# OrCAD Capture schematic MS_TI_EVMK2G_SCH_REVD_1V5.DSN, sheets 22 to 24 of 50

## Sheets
22 21. HDMI TRANSMITTER: size C; title: HDMI TRASMITTER
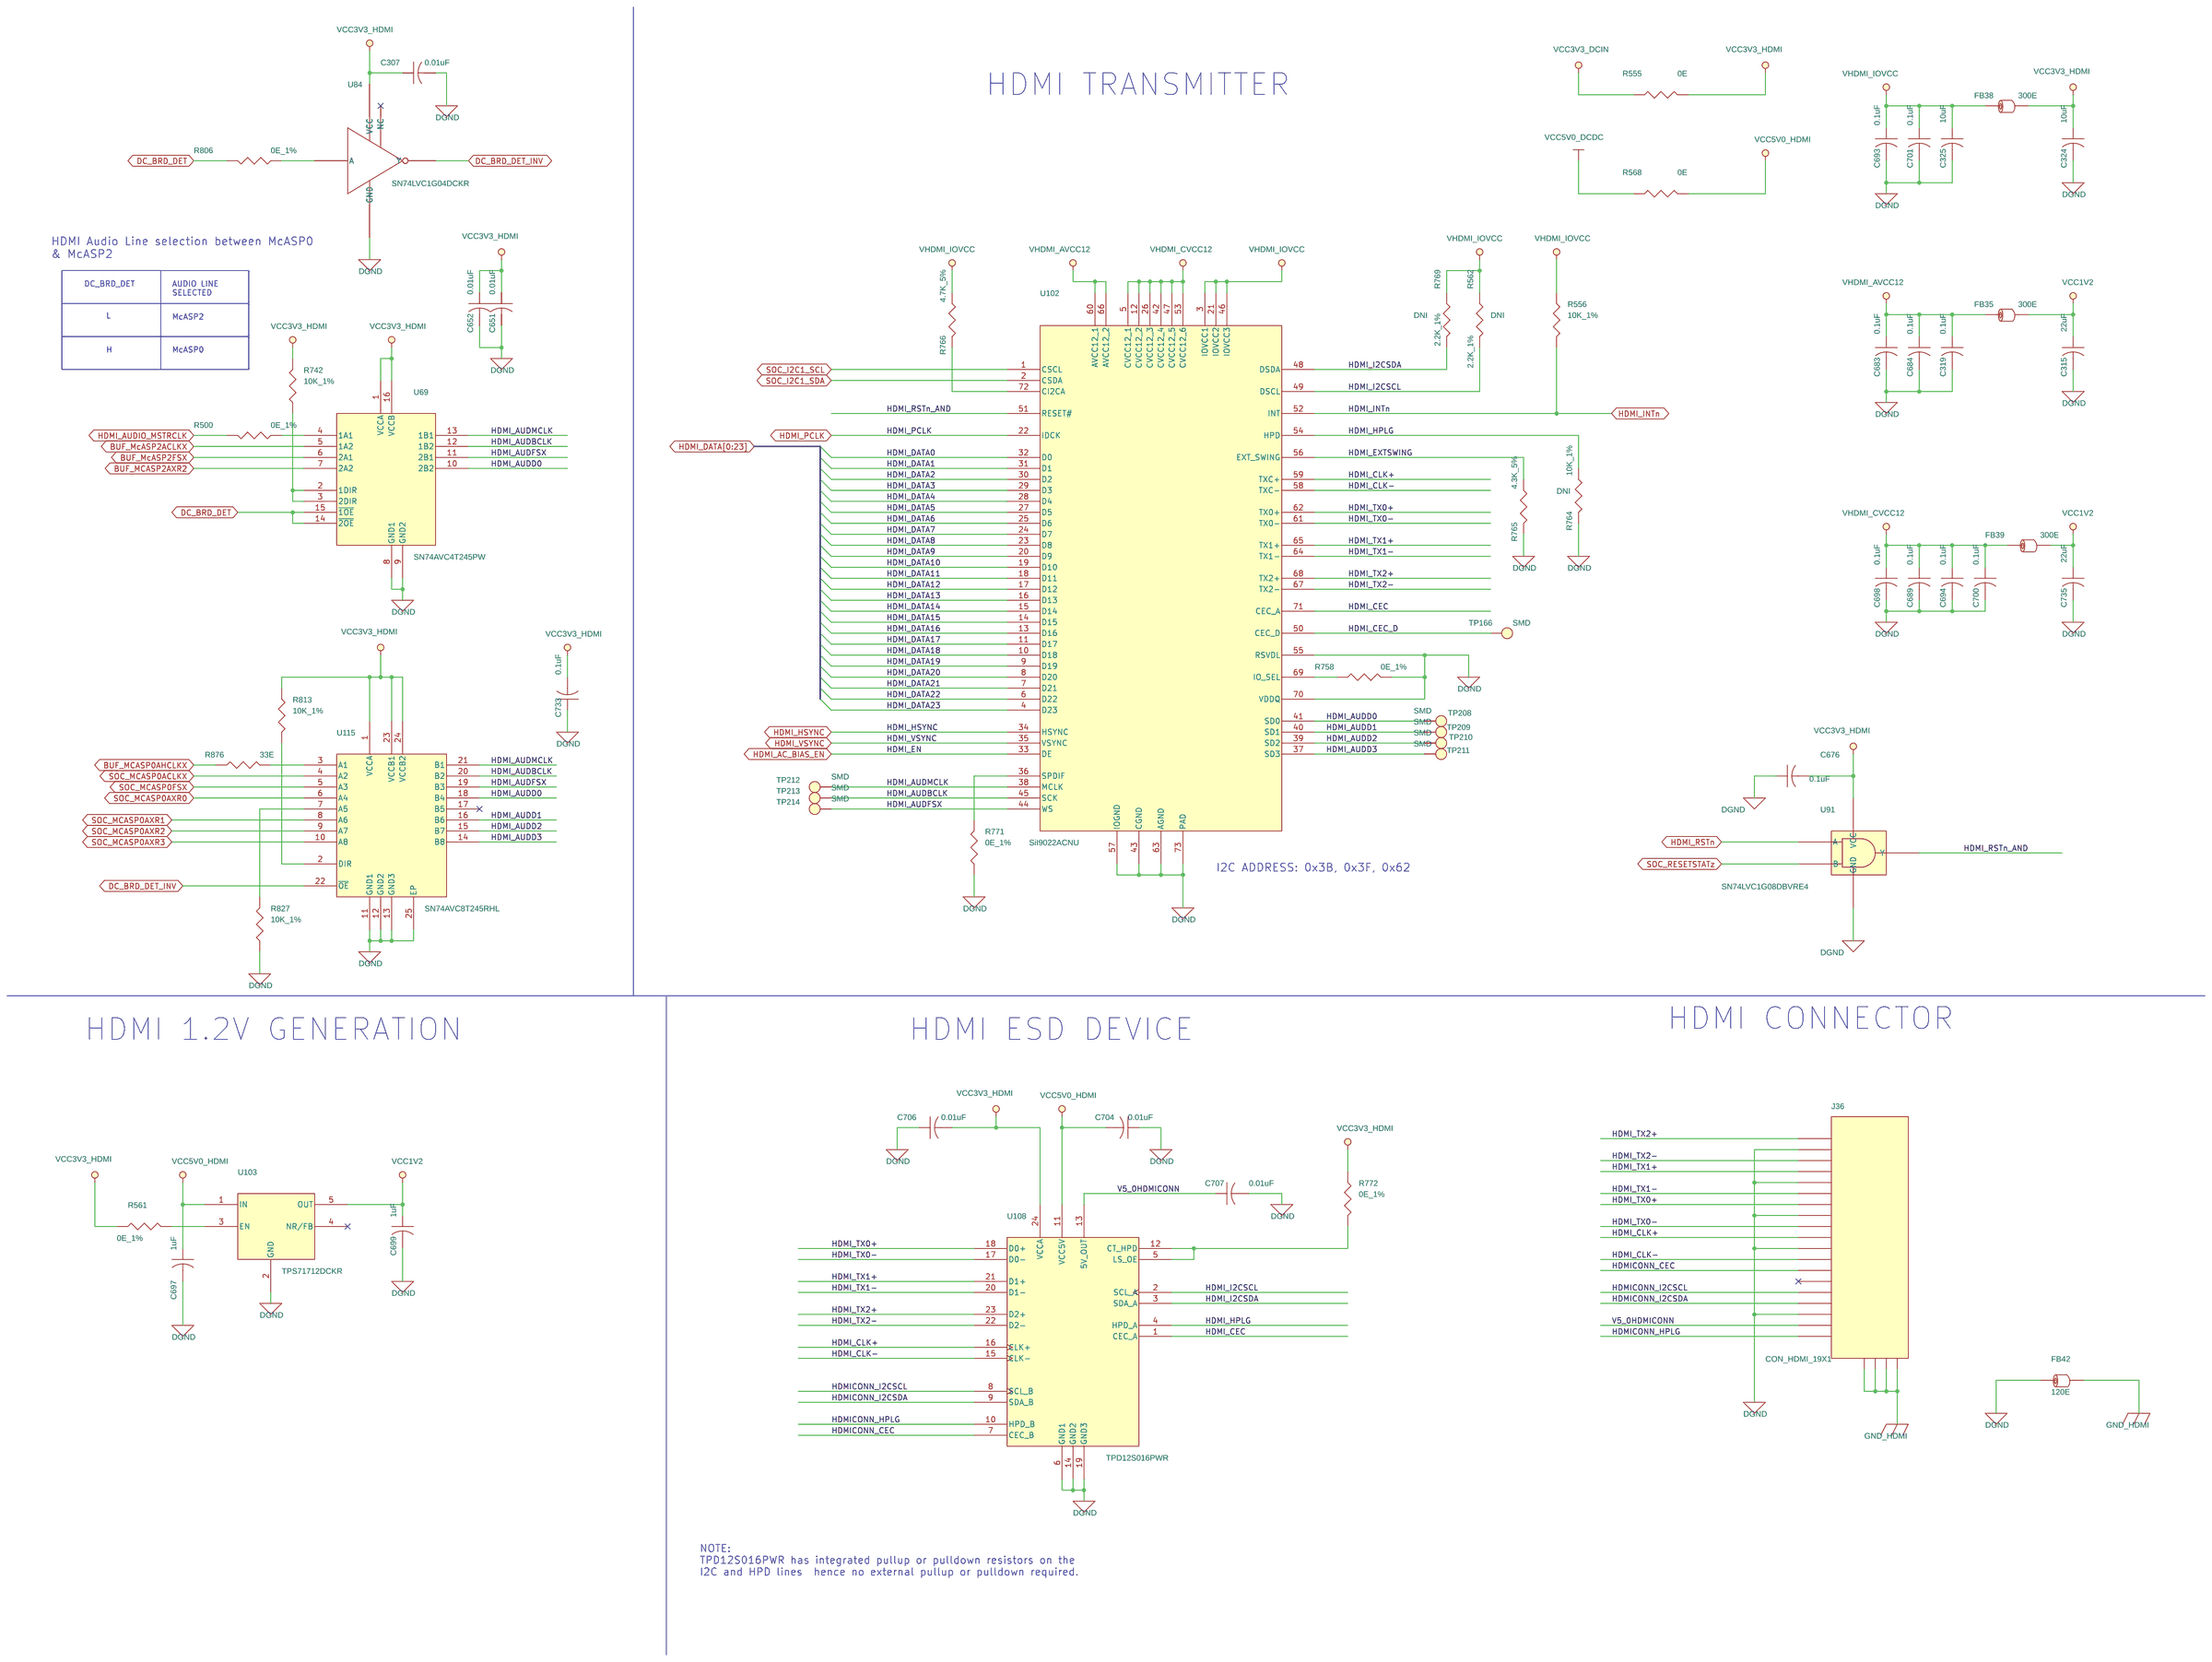
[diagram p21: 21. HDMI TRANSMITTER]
23 22. AUDIO CODEC: size C; title: AUDIO CODEC
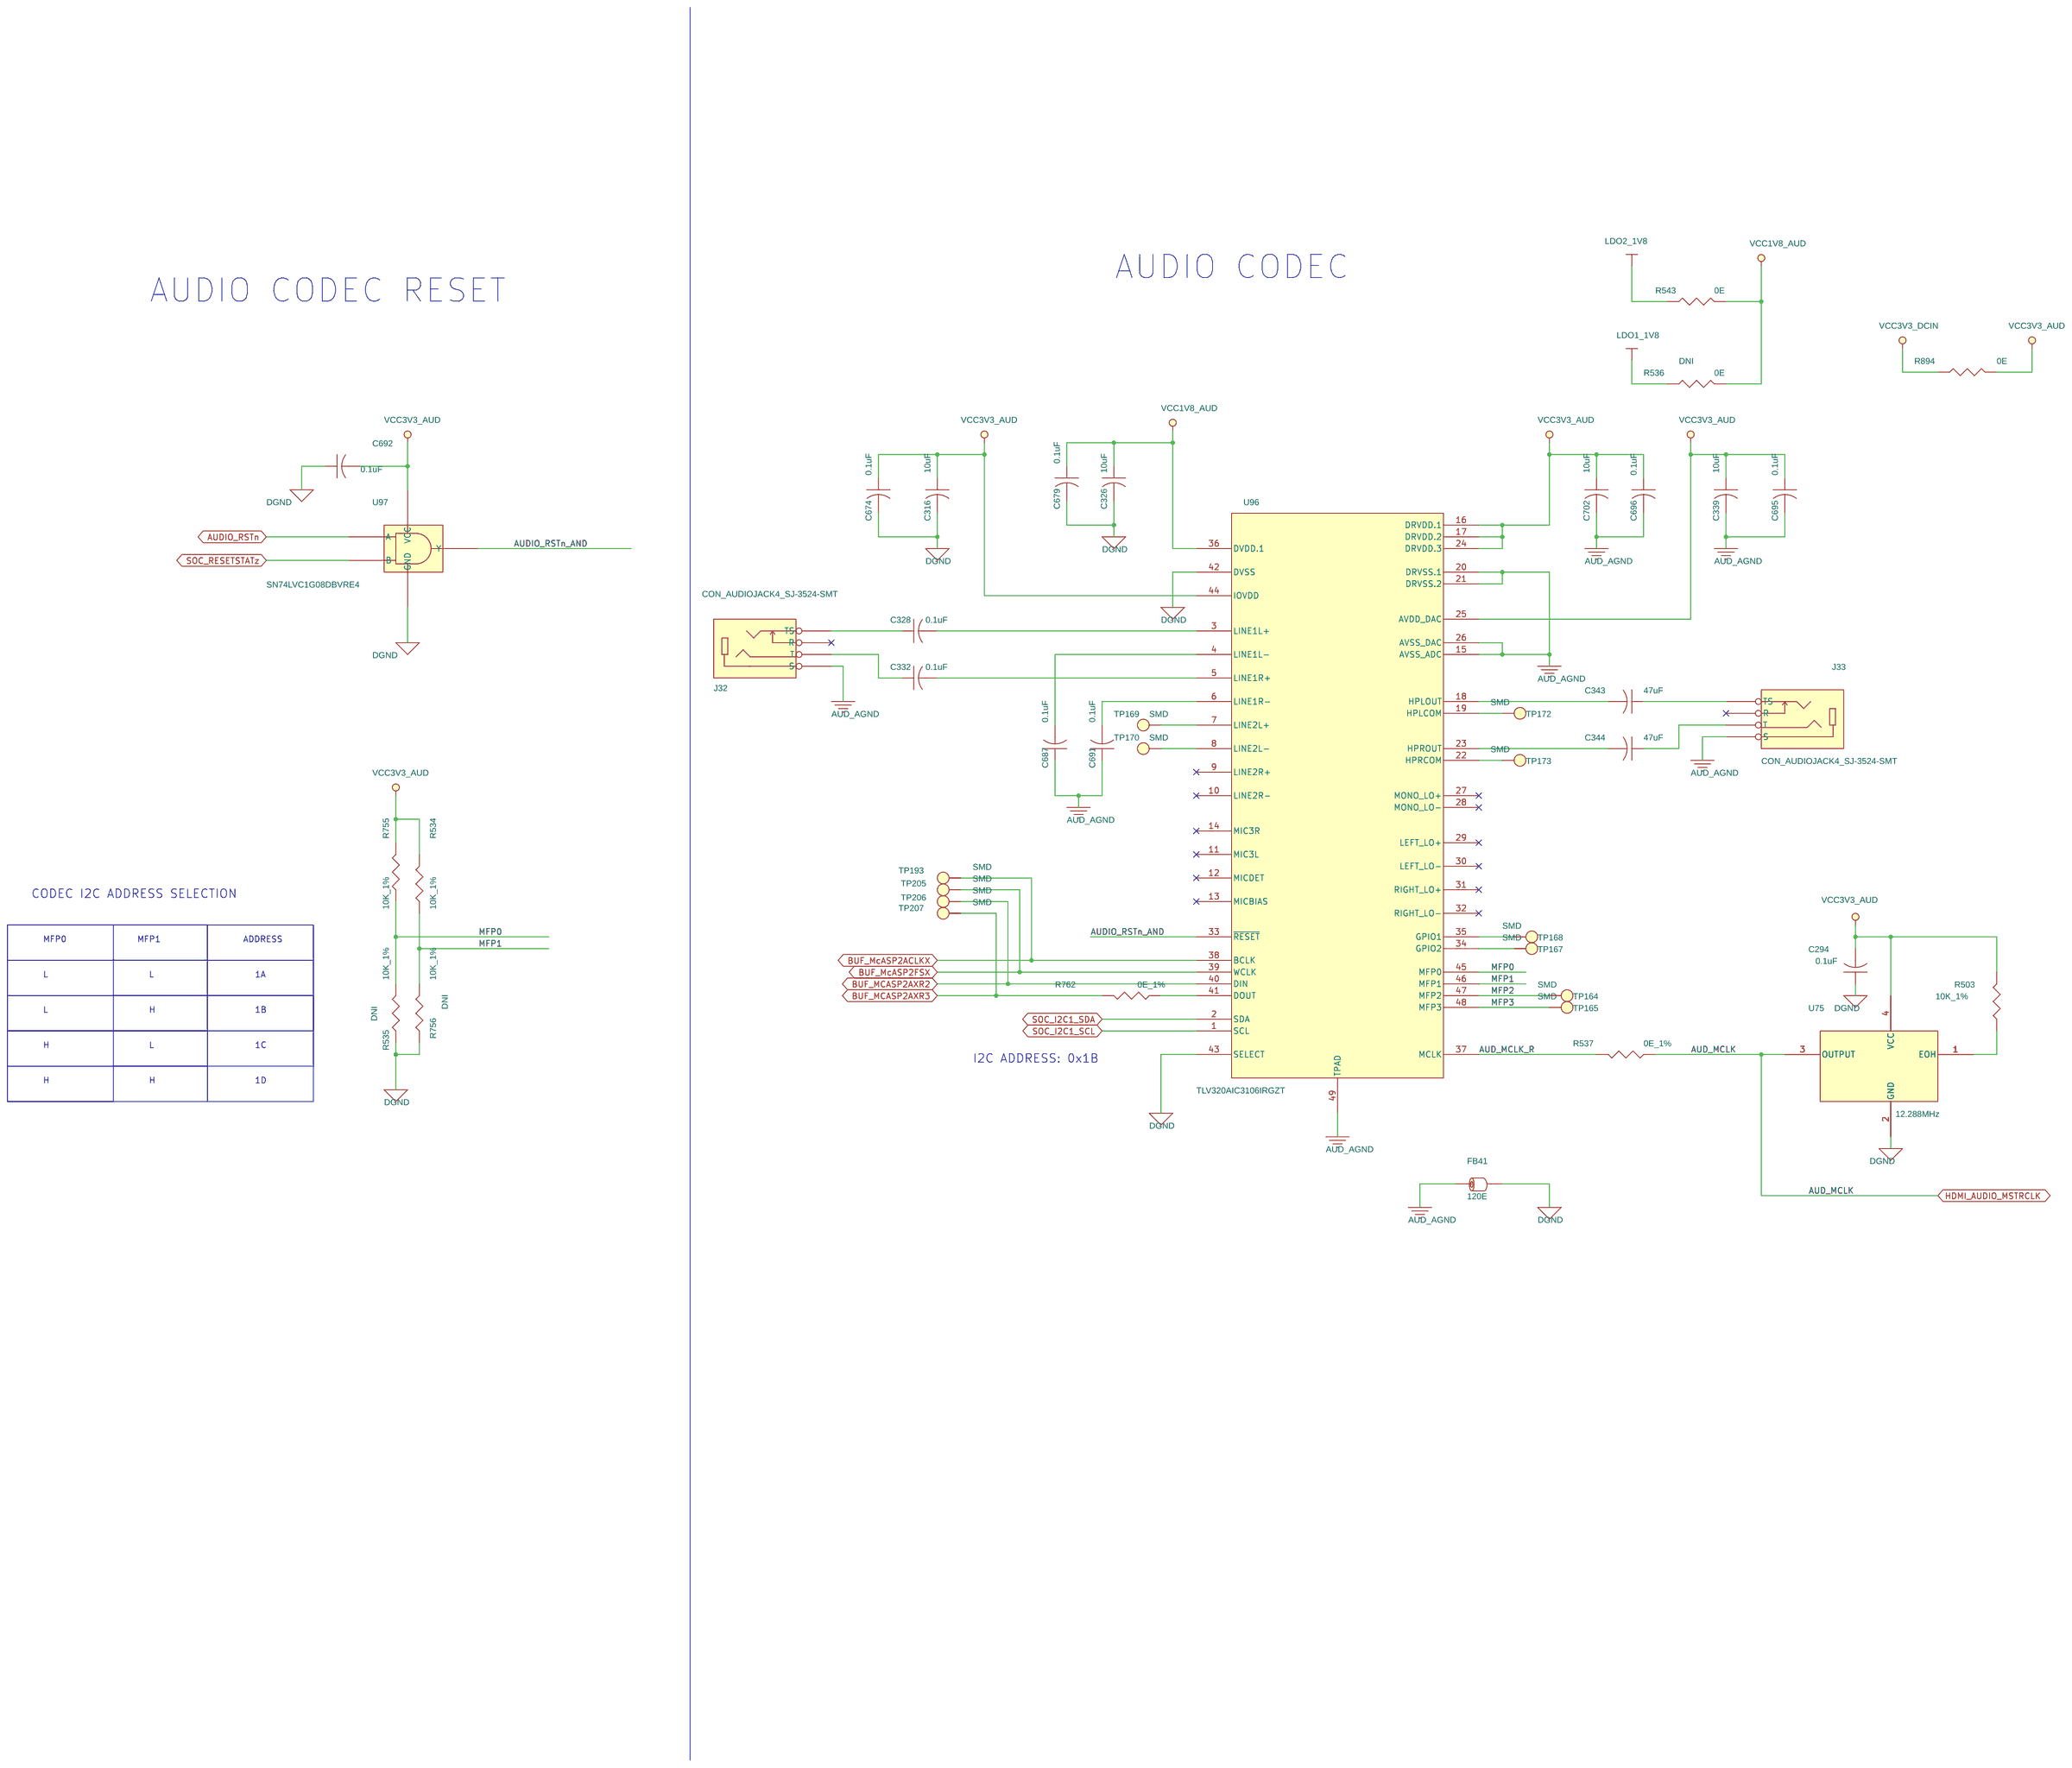
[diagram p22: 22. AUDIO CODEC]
24 23. AUDIO BUFFERS: size C; title: MCASP2 BUFFERS FOR COM8 , HDMI& AUDIO CODEC
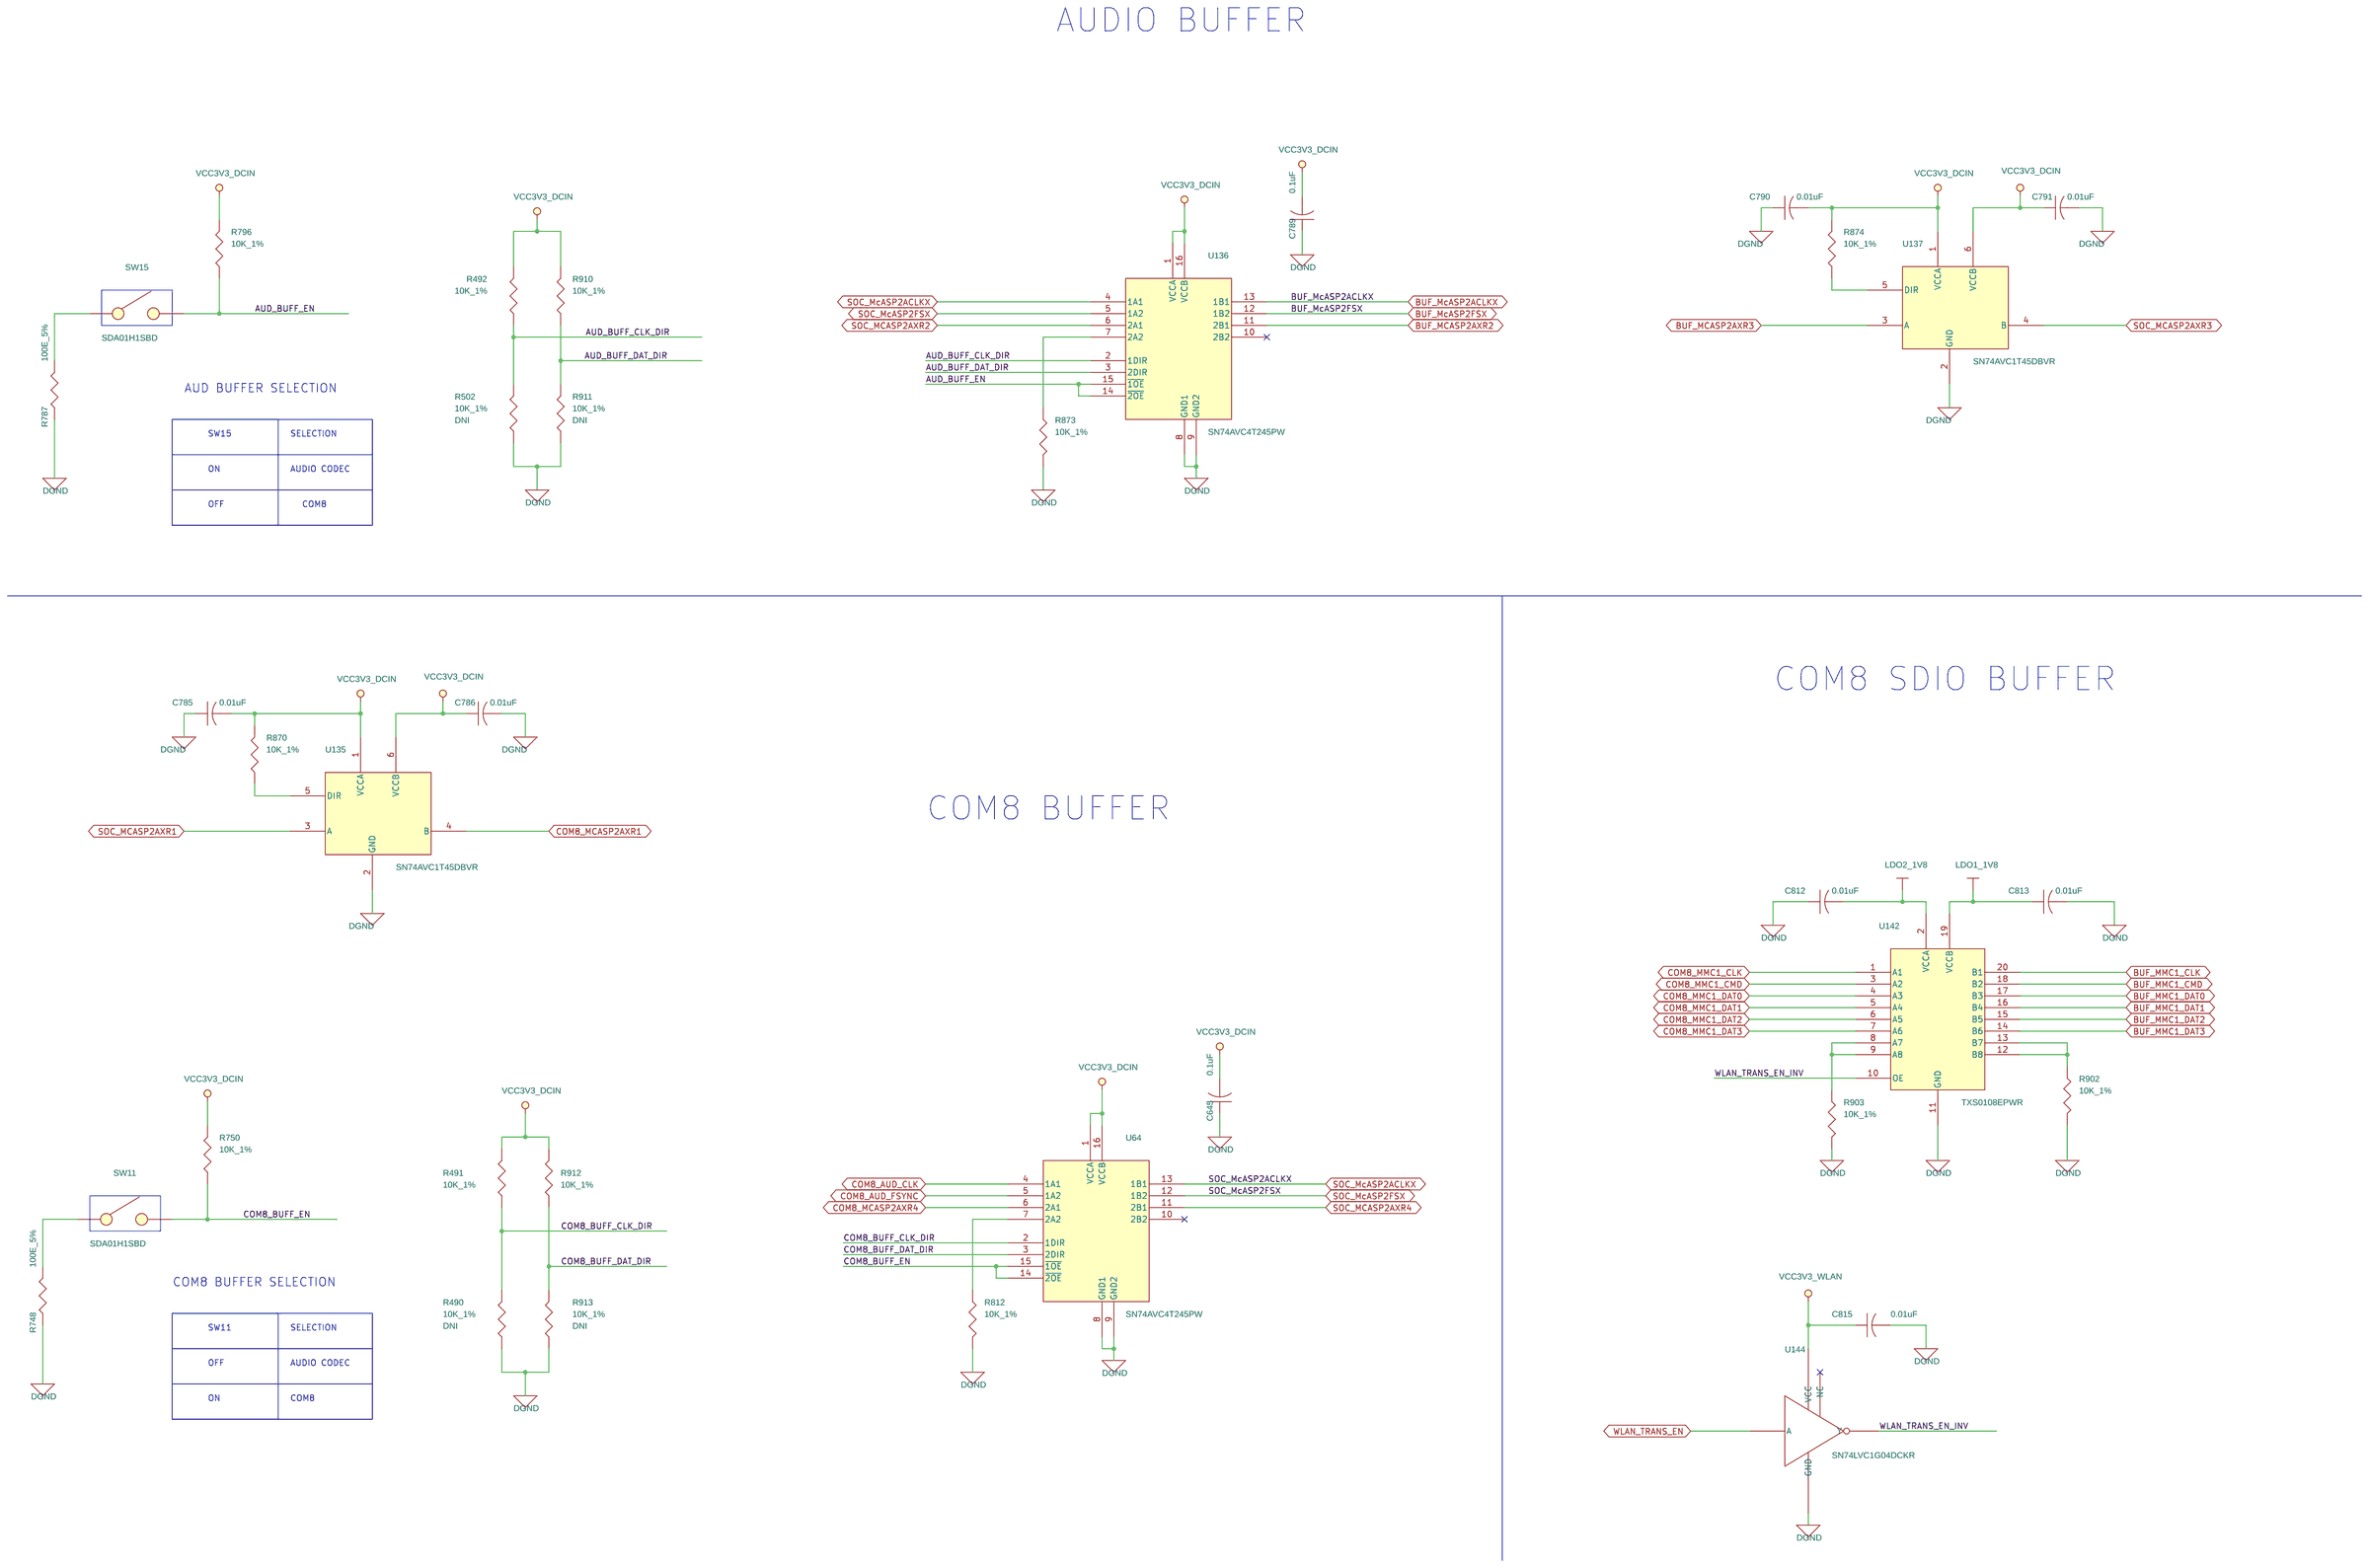
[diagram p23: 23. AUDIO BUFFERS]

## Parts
sheet 21. HDMI TRANSMITTER
C307  0.01uF  [CAP0402]
C315  22uF  [CAP0805]
C319  0.1uF  [CAP0402]
C324  10uF  [CAP0805]
C325  10uF  [CAP0805]
C651  0.01uF  [CAP0402]
C652  0.01uF  [CAP0201]
C676  0.1uF  [CAP0402]
C683  0.1uF  [CAP0402]
C684  0.1uF  [CAP0402]
C689  0.1uF  [CAP0402]
C693  0.1uF  [CAP0402]
C694  0.1uF  [CAP0402]
C697  1uF  [CAP0402]
C698  0.1uF  [CAP0402]
C699  1uF  [CAP0402]
C700  0.1uF  [CAP0402]
C701  0.1uF  [CAP0402]
C704  0.01uF  [CAP0402]
C706  0.01uF  [CAP0402]
C707  0.01uF  [CAP0402]
C733  0.1uF  [CAP0402]
C735  22uF  [CAP0805]
FB35  300E  [IND0603]
FB38  300E  [IND0603]
FB39  300E  [IND0603]
FB42  120E  [IND0402]
J36  CON_HDMI_19X1  [CON_19X1_10029449-001RLF_S_R_S]
R500  0E_1%  [RES0402]
R555  0E  [RES0402]
R556  10K_1%  [RES0402]
R561  0E_1%  [RES0402]
R562  2.2K_1%  [RES0402]
R568  0E  [RES0402]
R742  10K_1%  [RES0402]
R758  0E_1%  [RES0402]
R764  10K_1%  [RES0402]
R765  4.3K_5%  [RES0402]
R766  4.7K_5%  [RES0402]
R769  2.2K_1%  [RES0402]
R771  0E_1%  [RES0402]
R772  0E_1%  [RES0402]
R806  0E_1%  [RES0402]
R813  10K_1%  [RES0402]
R827  10K_1%  [RES0402]
R876  33E  [RES0402]
TP166  SMD  [TP20_SMD]
TP208  SMD  [TP40_SMD]
TP209  SMD  [TP40_SMD]
TP210  SMD  [TP40_SMD]
TP211  SMD  [TP40_SMD]
TP212  SMD  [TP40_SMD]
TP213  SMD  [TP40_SMD]
TP214  SMD  [TP40_SMD]
U69  SN74AVC4T245PW  [TSSOP16_25-59_205X180]
U84  SN74LVC1G04DCKR  [SC70-5]
U91  SN74LVC1G08DBVRE4  [SOT23-5]
U102  SiI9022ACNU  [QFN72_19-68_395X395]
U103  TPS71712DCKR  [SC70-5]
U108  TPD12S016PWR  [TSSOP24_25-59_315X180]
U115  SN74AVC8T245RHL  [QFN24_19-68_225X145]
sheet 22. AUDIO CODEC
C294  0.1uF  [CAP0402]
C316  10uF  [CAP0805]
C326  10uF  [CAP0805]
C328  0.1uF  [CAP0402]
C332  0.1uF  [CAP0402]
C339  10uF  [CAP0805]
C343  47uF  [CAP1206]
C344  47uF  [CAP1206]
C674  0.1uF  [CAP0402]
C679  0.1uF  [CAP0402]
C687  0.1uF  [CAP0402]
C691  0.1uF  [CAP0402]
C692  0.1uF  [CAP0402]
C695  0.1uF  [CAP0402]
C696  0.1uF  [CAP0402]
C702  10uF  [CAP0805]
FB41  120E  [IND0402]
J32  CON_AUDIOJACK4_SJ-3524-SMT  [CON_AV4_SJ-3524-SMT-1_R_S]
J33  CON_AUDIOJACK4_SJ-3524-SMT  [CON_AV4_SJ-3524-SMT-1_R_S]
R503  10K_1%  [RES0402]
R534  10K_1%  [RES0402]
R535  10K_1%  [RES0402]
R536  0E  [RES0402]
R537  0E_1%  [RES0402]
R543  0E  [RES0402]
R755  10K_1%  [RES0402]
R756  10K_1%  [RES0402]
R762  0E_1%  [RES0402]
R894  0E  [RES0402]
TP164  SMD  [TP40_SMD]
TP165  SMD  [TP40_SMD]
TP167  SMD  [TP40_SMD]
TP168  SMD  [TP40_SMD]
TP169  SMD  [TP40_SMD]
TP170  SMD  [TP40_SMD]
TP172  SMD  [TP40_SMD]
TP173  SMD  [TP40_SMD]
TP193  SMD  [TP40_SMD]
TP205  SMD  [TP40_SMD]
TP206  SMD  [TP40_SMD]
TP207  SMD  [TP40_SMD]
U75  12.288MHz  [OSC4_CB3_305X205_SMD]
U96  TLV320AIC3106IRGZT  [VQFN48_19-68_285X285]
U97  SN74LVC1G08DBVRE4  [SOT23-5]
sheet 23. AUDIO BUFFERS
C645  0.1uF  [CAP0402]
C785  0.01uF  [CAP0402]
C786  0.01uF  [CAP0402]
C789  0.1uF  [CAP0402]
C790  0.01uF  [CAP0402]
C791  0.01uF  [CAP0402]
C812  0.01uF  [CAP0402]
C813  0.01uF  [CAP0402]
C815  0.01uF  [CAP0402]
R490  10K_1%  [RES0402]
R491  10K_1%  [RES0402]
R492  10K_1%  [RES0402]
R502  10K_1%  [RES0402]
R748  100E_5%  [RES0402]
R750  10K_1%  [RES0402]
R787  100E_5%  [RES0402]
R796  10K_1%  [RES0402]
R812  10K_1%  [RES0402]
R870  10K_1%  [RES0402]
R873  10K_1%  [RES0402]
R874  10K_1%  [RES0402]
R902  10K_1%  [RES0402]
R903  10K_1%  [RES0402]
R910  10K_1%  [RES0402]
R911  10K_1%  [RES0402]
R912  10K_1%  [RES0402]
R913  10K_1%  [RES0402]
SW11  SDA01H1SBD  [SW2_100X324-80_180X300_SMD]
SW15  SDA01H1SBD  [SW2_100X324-80_180X300_SMD]
U64  SN74AVC4T245PW  [TSSOP16_25-59_205X180]
U135  SN74AVC1T45DBVR  [SOT23-6]
U136  SN74AVC4T245PW  [TSSOP16_25-59_205X180]
U137  SN74AVC1T45DBVR  [SOT23-6]
U142  TXS0108EPWR  [TSSOP20_25-59_260X180]
U144  SN74LVC1G04DCKR  [SC70-5]

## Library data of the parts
C307 C651 C704 C706 C707 C785 C786 C790 C791 C812 C813 C815 = CAP: CAP CERAMIC 0.01uF 16V 10% X7R 0402; Alternate_mfr_name_A: AVX CORPORATION; Alternate_mfr_name_B: KEMET; Alternate_mfr_name_D: TDK CORPORATION; Alternate_mfr_part_number_A: 0402YC103KAT2A; Alternate_mfr_part_number_B: C0402C103K4RACTU; Alternate_mfr_part_number_D: C1005X7R1C103K; Chkd/date: SHREESHAIL/180506; Crtd /date: MAZHAR/110506; Custom_Duty: 15%; Customs_HS_Code: 85322990; Distributor_name: DIGIKEY; Distributor_name_A: DIGIKEY; Distributor_name_B: DIGIKEY; Distributor_name_D: DIGIKEY; Distributor_part_number: PCC103BQCT-ND; Distributor_part_number_A: 478-1114-1-ND; Distributor_part_number_B: 399-1038-1-ND; Distributor_part_number_D: 445-1262-1-ND; Height: 0.55MM; Mfr_name: PANASONIC-ECG; Mfr_part_number: ECJ-0EB1C103K; Mistral Part No: 120009030032-R; Package: 0402; Part_type: CAPACITORS\CERAMIC; Project: VOCERA; RoHS: RoHS; Tolerance: 10%; Voltage: 16V; Datasheet: Y:\MIS_DATABASE\DATASHEETS\CAPACITORS\PAN-ECJ.PDF
C315 C735 = CAP: CAP CERAMIC 22uF 16V 10% X5R 0805; Chkd/date: MAZHAR/291110; Crtd /date: BAVISH/271110; Custom_Duty: 15%; Customs_HS_Code: 85322990; Distributor_name: NA; Distributor_part_number: NA; Height: 1.45MM; Mfr_name: TDK CORPORATION; Mfr_part_number: C2012X5R1C226K; Mistral Part No: 120010110025-R; Package: 0805; Part_type: CAPACITORS\CERAMIC; Project: EM-FLS; RoHS: RoHS; Temperature: -55°C+85°C; Tolerance: 10%; Voltage: 16V; Wattage: NA; Weight: NA; Datasheet: Y:\MIS_DATABASE\DATASHEETS\CAPACITORS\C2012.PDF
C294 C319 C328 C332 C645 C674 C676 C679 C683 C684 C687 C689 C691-C696 C698 C700 C701 C733 C789 = CAP: CAP CERAMIC 0.1uF 16V 10% X7R 0402; Alternate_mfr_name_A: KEMET; Alternate_mfr_part_number_A: C0402C104K4RACT; Chkd/date: MAZHAR/281108; Crtd /date: MAZHAR/030907; Custom_Duty: 15%; Customs_HS_Code: 85322990; Distributor_name: DIGIKEY; Distributor_name_A: DIGIKEY; Distributor_part_number: 490-3261-1-ND; Distributor_part_number_A: 399-3521-1-ND; Height: 0.55MM; Mfr_name: MURATA; Mfr_part_number: GRM155R71C104KA88D; Mistral Part No: 120009030060-R; Package: 0402; Part_type: CAPACITORS\CERAMIC; Project: SMART VIEW_IP CAMERA; Tolerance: 10%; Voltage: 16V; Datasheet: Y:\MIS_DATABASE\DATASHEETS\CAPACITORS\GRM188SERIES.PDF
C316 C324-C326 C339 C702 = CAP: CAP CERAMIC 10uF 16V 10% X5R 0805; Alternate_mfr_name_A: TAIYO YUDEN; Alternate_mfr_part_number_A: EMK212BJ106KG-T; Chkd/date: RAVI/020511; Crtd /date: BAVISH/290411; Custom_Duty: 15%; Customs_HS_Code: 85322990; Distributor_name: DIGIKEY; Distributor_name_A: DIGIKEY; Distributor_part_number: 478-5165-1-ND; Distributor_part_number_A: 587-1295-1-ND; Height: 1.40MM; Mfr_name: AVX CORPORATION; Mfr_part_number: 0805YD106KAT2A; Mistral Part No: 120011040011-R; Package: 0805; Part_type: CAPACITORS\CERAMIC; Project: AOD_POD-RF; RoHS: RoHS; Temperature: -55°C+85°C; Tolerance: 10%; Voltage: 16V; Wattage: NA; Weight: NA; Datasheet: Y:\MIS_DATABASE\DATASHEETS\CAPACITORS\AVX_CERAMIC.PDF
C652 = CAP: CAP CERAMIC 0.01uF 10V 10% X5R 0201; Chkd/date: MAZHAR/010211; Crtd /date: BAVISH/131010; Custom_Duty: 15%; Customs_HS_Code: 85322990; Distributor_name: DIGIKEY; Distributor_part_number: 445-1793-1-ND; Height: 0.33MM; Mfr_name: TDK CORPORATION; Mfr_part_number: C0603X5R1A103K; Mistral Part No: 120011010015-R; Package: 0201; Part_type: CAPACITORS\CERAMIC; Project: IDMATEK2; RoHS: RoHS; Temperature: -55°C+85°C; Tolerance: 10%; Voltage: 10V; Wattage: NA; Weight: NA; Datasheet: Y:\MIS_DATABASE\DATASHEETS\CAPACITORS\TDK_CAP.PDF
C697 C699 = CAP: CAP CERAMIC 1uF 10V 10% X5R 0402; Chkd/date: BALACHANDAR/160514; Crtd /date: SARANYA/060514; Custom_Duty: 15%; Customs_HS_Code: 85322990; Distributor_name: DIGIKEY; Distributor_part_number: 478-4596-1-ND; Height: 0.56MM; Mfr_name: AVX CORPORATION; Mfr_part_number: 0402ZD105KAT2A; Mistral Part No: 120014050010-R; Package: 0402; Part_type: CAPACITORS\CERAMIC; Project: AEGIS GP BETA2; RoHS: RoHS; Temperature: -55°C+85°C; Tolerance: 10%; Voltage: 10V; Wattage: NA; Weight: NA; Datasheet: Y:\MIS_DATABASE\DATASHEETS\CAPACITORS\AVX_MLC.PDF
FB35 FB38 FB39 = INDUCTOR_FERRITE: IND FERRITE CHIP 300E 500mA 0603; Chkd/date: VASANTHA/190614; Crtd /date: NAVEED/160614; Custom_Duty: 24%; Customs_HS_Code: 85437099; Distributor_name: DIGIKEY; Distributor_part_number: 445-2171-1-ND; Height: 0.75MM; Mfr_name: TDK CORPORATION; Mfr_part_number: MMZ1608R301A; Mistral Part No: 130014060028-R; Package: 0603; Part_type: INDUCTOR; Project: AEGIS_POM; RoHS: RoHS; Temperature: -55°C+125°C; Tolerance: NA; Voltage: NA; Wattage: NA; Weight: NA; Datasheet: Y:\MIS_DATABASE\DATASHEETS\DISCRETES\INDUCTORS\MMZSER.PDF
FB41 FB42 = INDUCTOR_FERRITE: IND BEAD CHIP 120E 1.2A 0402; Chkd/date: ASHOK/240212; Crtd /date: BAVISH/060711; Custom_Duty: 24%; Customs_HS_Code: 85437099; Distributor_name: DIGIKEY; Distributor_part_number: 445-2981-1-ND; Height: 0.55MM; Mfr_name: TDK CORPORATION; Mfr_part_number: MPZ1005S121C; Mistral Part No: 130011070007-R; Package: 0402; Part_type: INDUCTOR; Project: SVDU; RoHS: RoHS; Temperature: -40°C+85°C; Tolerance: NA; Voltage: NA; Wattage: NA; Weight: 1mg; Datasheet: Y:\MIS_DATABASE\DATASHEETS\DISCRETES\INDUCTORS\MPZ1005.PDF
J36 = CON_HDMI_19X1: CON RECEPTACLE HDMI TYPE A RT SMD; Chkd/date: SUHAS/290311; Crtd /date: MUDDU/060510; Custom_Duty: 24%; Customs_HS_Code: 85369090; Distributor_name: DIGIKEY; Distributor_part_number: 609-1010-1-ND; Height: 6.30MM; Mfr_name: FCI; Mfr_part_number: 10029449-001RLF; Mistral Part No: 150010050001; Package: SMD; Part_type: CONNECTOR\MISCELLANEOUS; Project: SHIVA; RoHS: RoHS; Temperature: NA; Weight: NA; Datasheet: Y:\MIS_DATABASE\DATASHEETS\CONNECTORS\10029449-001RLF.PDF
R500 R537 R561 R758 R762 R771 R772 R806 = RESISTOR: RES 0E 1/16W 1% 0402; Chkd/date: MAZHAR/220709; Crtd /date: USMAN/270109; Custom_Duty: 15%; Customs_HS_Code: 85332119; Distributor_name: NA; Distributor_part_number: NA; Height: 0.40MM; Mfr_name: YAGEO AMERICA; Mfr_part_number: RC0402FR-070RL; Mistral Part No: 110009030085-P; Package: 0402; Part_type: RESISTORS\FIXED; Project: OMAP_EVM; RoHS: Pb-Free; Tolerance: 1%; Wattage: 1/16W; Datasheet: Y:\MIS_DATABASE\DATASHEETS\RESISTORS\CRCW0603.PDF
R543 R555 R568 R894 = RESISTOR: RES 0E 1/10W 5% 0402; Chkd/date: NAVEED/241114; Crtd /date: NAVEED/201014; Custom_Duty: 15%; Customs_HS_Code: 85332119; Distributor_name: DIGIKEY; Distributor_part_number: P0.0JCT-ND; Height: 0.40MM; Mfr_name: PANASONIC-ECG; Mfr_part_number: ERJ-2GE0R00X; Mistral Part No: 110014100008-R; Package: 0402; Part_type: RESISTORS\FIXED; Project: AEGIS POM; RoHS: RoHS; Tolerance: 5%; Wattage: 1/10W; Datasheet: Y:\MIS_DATABASE\DATASHEETS\RESISTORS\ERJ12.PDF
R491 R492 R503 R534 R556 R742 R750 R755 R796 R812 R813 R827 R870 R873 R874 R902 R903 R910 R912 = RESISTOR: RES 10K 1/16W 1% 0402; Alternate_mfr_name_A: AVX CORPORATION; Alternate_mfr_name_B: PANASONIC-ECG-ECG; Alternate_mfr_name_C: YAGEO AMERICA; Alternate_mfr_name_D: VISHAY; Alternate_mfr_part_number_A: CR05-103F-H; Alternate_mfr_part_number_B: ERJ-2RKF1002X; Alternate_mfr_part_number_C: 9C04021A1002FLHF3; Alternate_mfr_part_number_D: CRCW040210K0FKED; Chkd/date: SHREESHAIL/310506; Crtd /date: GEETHA/290506; Custom_Duty: 15%; Customs_HS_Code: 85332119; Distributor_name: DIGIKEY; Distributor_name_A: NA; Distributor_name_B: DIGIKEY; Distributor_name_C: DIGIKEY; Distributor_name_D: DIGIKEY; Distributor_part_number: 311-10.0KLRTR-ND; Distributor_part_number_A: NA; Distributor_part_number_B: P10.0KLCT-ND; Distributor_part_number_C: 311-10.0KLCT-ND; Distributor_part_number_D: 541-10.0KLCT-ND; Height: 0.40MM; Mfr_name: YAGEO AMERICA; Mfr_part_number: RC0402FR-0710KL; Mistral Part No: 110009030220-P; Package: 0402; Part_type: RESISTORS\FIXED; Project: VOCERA; RoHS: Pb-Free; Tolerance: 1%; Wattage: 1/16W; Datasheet: Y:\MIS_DATABASE\DATASHEETS\RESISTORS\YAGEO-RC0402.PDF
R562 R769 = RESISTOR: RES 2.2K 1/16W 1% 0402; Chkd/date: NAVEED/241114; Crtd /date: VASANTHA/101114; Custom_Duty: 15%; Customs_HS_Code: 85332119; Distributor_name: DIGIKEY; Distributor_part_number: 311-2.20KLRCT-ND; Height: 0.40MM; Loading: DNI; Mfr_name: YAGEO AMERICA; Mfr_part_number: RC0402FR-072K2L; Mistral Part No: 110014110004-R; Package: 0402; Part_type: RESISTORS\FIXED; Project: GALILEO_EVM; RoHS: RoHS; Temperature: -55°C+155°C; Tolerance: 1%; Voltage: NA; Wattage: 1/16W; Weight: NA; Datasheet: Y:\MIS_DATABASE\DATASHEETS\RESISTORS\RC0402FR.PDF
R490 R502 R535 R756 R764 R911 R913 = RESISTOR: RES 10K 1/16W 1% 0402; Alternate_mfr_name_A: AVX CORPORATION; Alternate_mfr_name_B: PANASONIC-ECG-ECG; Alternate_mfr_name_C: YAGEO AMERICA; Alternate_mfr_name_D: VISHAY; Alternate_mfr_part_number_A: CR05-103F-H; Alternate_mfr_part_number_B: ERJ-2RKF1002X; Alternate_mfr_part_number_C: 9C04021A1002FLHF3; Alternate_mfr_part_number_D: CRCW040210K0FKED; Chkd/date: SHREESHAIL/310506; Crtd /date: GEETHA/290506; Custom_Duty: 15%; Customs_HS_Code: 85332119; Distributor_name: DIGIKEY; Distributor_name_A: NA; Distributor_name_B: DIGIKEY; Distributor_name_C: DIGIKEY; Distributor_name_D: DIGIKEY; Distributor_part_number: 311-10.0KLRTR-ND; Distributor_part_number_A: NA; Distributor_part_number_B: P10.0KLCT-ND; Distributor_part_number_C: 311-10.0KLCT-ND; Distributor_part_number_D: 541-10.0KLCT-ND; Height: 0.40MM; Loading: DNI; Mfr_name: YAGEO AMERICA; Mfr_part_number: RC0402FR-0710KL; Mistral Part No: 110009030220-P; Package: 0402; Part_type: RESISTORS\FIXED; Project: VOCERA; RoHS: Pb-Free; Tolerance: 1%; Wattage: 1/16W; Datasheet: Y:\MIS_DATABASE\DATASHEETS\RESISTORS\YAGEO-RC0402.PDF
R765 = RESISTOR: RES 4.3K 1/16W 5% 0402; Chkd/date: VASANTHA/190614; Crtd /date: NAVEED/160614; Custom_Duty: 15%; Customs_HS_Code: 85332119; Distributor_name: DIGIKEY; Distributor_part_number: RMCF0402JT4K30CT-ND; Height: 0.40MM; Mfr_name: STACKPOLE ELECTRONICS; Mfr_part_number: RMCF0402JT4K30; Mistral Part No: 110014060029-R; Package: 0402; Part_type: RESISTORS\FIXED; Project: AEGIS_POM; RoHS: RoHS; Temperature: -55°C+155°C; Tolerance: 5%; Voltage: NA; Wattage: 1/16W; Weight: NA; Datasheet: Y:\MIS_DATABASE\DATASHEETS\RESISTORS\RMCF-SERIES1.PDF
R766 = RESISTOR: RES 4.7K 1/16W 5% 0402; Chkd/date: VASANTHA/190614; Crtd /date: NAVEED/160614; Custom_Duty: 15%; Customs_HS_Code: 85332119; Distributor_name: DIGIKEY; Distributor_part_number: RMCF0402JT4K70CT-ND; Height: 0.40MM; Mfr_name: STACKPOLE ELECTRONICS; Mfr_part_number: RMCF0402JT4K70; Mistral Part No: 110014060028-R; Package: 0402; Part_type: RESISTORS\FIXED; Project: AEGIS_POM; RoHS: RoHS; Temperature: -55°C+155°C; Tolerance: 5%; Voltage: NA; Wattage: 1/16W; Weight: NA; Datasheet: Y:\MIS_DATABASE\DATASHEETS\RESISTORS\RMCF-SERIES1.PDF
R876 = RESISTOR: RES 33E 1/16W 5% 0402; Alternate_mfr_name_A: AVX CORPORATION; Alternate_mfr_name_B: ROHM; Alternate_mfr_name_C: YAGEO AMERICA; Alternate_mfr_name_D: YAGEO AMERICA; Alternate_mfr_part_number_A: CR05-330J-H; Alternate_mfr_part_number_B: MCR01MZPJ330; Alternate_mfr_part_number_C: 9C04021A33R0JLHF3; Alternate_mfr_part_number_D: RC0402JR-0733RL; Chkd/date: SHREESHAIL/200406; Crtd /date: GEETHA/190406; Custom_Duty: 15%; Customs_HS_Code: 85332119; Distributor_name: DIGIKEY; Distributor_name_A: NA; Distributor_name_B: DIGIKEY; Distributor_name_C: DIGIKEY; Distributor_name_D: DIGIKEY; Distributor_part_number: P33JCT-ND; Distributor_part_number_A: NA; Distributor_part_number_B: RHM33JCT-ND; Distributor_part_number_C: 311-33JCT-ND; Distributor_part_number_D: 311-33JRCT-ND; Height: 0.40MM; Mfr_name: PANASONIC-ECG; Mfr_part_number: ERJ-2GEJ330X; Mistral Part No: 110009030699-R; Package: 0402; Part_type: RESISTORS\FIXED; Project: RED EYE; RoHS: RoHS; Tolerance: 5%; Wattage: 1/16W; Datasheet: Y:\MIS_DATABASE\DATASHEETS\RESISTORS\ERJ12.PDF
TP166 = TESTPOINT: TESTPOINT 20 SMD; Chkd/date: SHREESHAIL/171006; Crtd /date: MAZHAR/171006; Distributor_name: NA; Distributor_part_number: NA; Height: NA; Mfr_name: LOCAL; Mistral Part No: NA4; Part_type: MISC\TESTPOINT; Project: BT MODULE_CSRBC04
TP164 TP165 TP167-TP170 TP172 TP173 TP193 TP205-TP214 = TESTPOINT: TESTPOINT 40 SMD; Chkd/date: MAZHAR/190505; Crtd /date: MAZHAR/190505; Distributor_name: NA; Distributor_part_number: NA; Height: NA; Mfr_name: LOCAL; Mistral Part No: 130009030933; Part_type: MISC\TESTPOINT; Project: RAINIER-3
U64 U69 U136 = SN74AVC4T245PW_TSSOP16: IC 4-BIT DUAL SUPPLY BUS TRANSCEIVER TSSOP16; Chkd/date: SHREESHAIL/030506; Crtd /date: MAZHAR/270406; Custom_Duty: 15%; Customs_HS_Code: 85423100; Distributor_name: MOUSER; Distributor_part_number: 595-SN74AVC4T245PW; Height: 1.20MM; Mfr_name: TEXAS INSTRUMENTS; Mistral Part No: 141009030111-R; Package: TSSOP16; Part_type: ICS\DIGITAL\COMBINATIONAL; Project: VOCERA; RoHS: Sb/ Br FREE; Datasheet: Y:\MIS_DATABASE\DATASHEETS\ICS\DIGITAL\BUSTRANSCEIVER\SN74AVC4T245.PDF
U84 U144 = SN74LVC1G04DCKR_SC70-5: IC SINGLE INVERTER GATE SC70-5; Chkd/date: SUHAS/221010; Crtd /date: USMAN/150709; Custom_Duty: 15%; Customs_HS_Code: 85423100; Distributor_name: DIGIKEY; Distributor_part_number: 296-11600-1-ND; Height: 1.10MM; Mfr_name: TEXAS INSTRUMENTS; Mistral Part No: 141009070007-R; Part_type: ICS\DIGITAL\GATES; Project: BUG_BASE-II; RoHS: Sb/ Br FREE; Temperature: -40°C+85°C; Datasheet: Y:\MIS_DATABASE\DATASHEETS\ICS\DIGITAL\GATES\SN74LVC1G04-1.PDF
U91 U97 = SN74LVC1G08DBVRE4_SOT23-5: IC SINGLE 2-INPUT POSITIVE AND GATE SOT23-5; Chkd/date: SUHAS/221010; Crtd /date: USMAN/151008; Custom_Duty: 15%; Customs_HS_Code: 85423100; Distributor_name: DIGIKEY; Distributor_part_number: SN74LVC1G08DBVRE4-ND; Height: 1.45MM; Mfr_name: TEXAS INSTRUMENTS; Mistral Part No: 141009060026-R; Part_type: ICS\DIGITAL\GATES; Project: KHAN_MAIN; RoHS: Sb/ Br FREE; Temperature: -40°C+85°C; Datasheet: Y:\MIS_DATABASE\DATASHEETS\ICS\DIGITAL\GATES\SN74LVC1G08.PDF
U102 = SiI9022ACNU_QFN72: IC HDMI TRANSMITTER QFN72; Chkd/date: VASANTHA/230714; Crtd /date: MUDDU/310510; Custom_Duty: 15%; Customs_HS_Code: 85423100; Distributor_name: NA; Distributor_part_number: NA; Height: 0.90MM; Mfr_name: SILICON IMAGE; Mistral Part No: 141010060001; Package: QFN72; Part_type: ICS\DIGITAL\PERIPHERAL; Project: CENTAURUS; Temperature: -20°C+85°C; Weight: NA; Datasheet: Y:\MIS_DATABASE\DATASHEETS\ICS\DIGITAL\PERIPHERAL\SiI9022.PDF
U103 = TPS71711DCKR_SC70-5: IC LINEAR REGULATOR LDO 150mA SC70-5; Chkd/date: VASANTHA/210714; Crtd /date: NAVEED/200614; Custom_Duty: 15%; Customs_HS_Code: 85423100; Distributor_name: DIGIKEY; Distributor_part_number: 296-22480-1-ND; Height: 1.10MM; Mfr_name: TEXAS INSTRUMENTS; Mistral Part No: 142014060014-R; Part_type: ICS\POWER\VOLTAGE REGULATOR; Project: AEGIS_POM; RoHS: RoHS; Temperature: -55°C+150°C; Tolerance: NA; Voltage: NA; Wattage: NA; Weight: NA; Datasheet: Y:\MIS_DATABASE\DATASHEETS\ICS\POWER\TPS71711.PDF
U108 = TPD12S016PW_TSSOP24: IC HDMI COMPANION CHIP TSSOP24; Chkd/date: USMAN/090612; Crtd /date: BAVISH/180811; Custom_Duty: 15%; Customs_HS_Code: 85423100; Distributor_name: NA; Distributor_part_number: NA; Height: 1.20MM; Mfr_name: TEXAS INSTRUMENTS; Mistral Part No: 141011080021; Package: TSSOP24; Part_type: ICS\INTERFACE; Project: DM385EVM_BASE-BOARD; Temperature: -40°C+85°C; Tolerance: NA; Voltage: NA; Wattage: NA; Weight: NA; Datasheet: Y:\MIS_DATABASE\DATASHEETS\ICS\INTERFACE\TPD12S016.PDF
U115 = SN74AVC8T245RHL_QFN24: IC BUS TRANSCEIVER 8-BIT DUAL-SUPPLY QFN24; Chkd/date: RAGESH/050511; Crtd /date: BAVISH/290411; Custom_Duty: 15%; Customs_HS_Code: 85423100; Distributor_name: DIGIKEY; Distributor_part_number: 296-17859-1-ND; Height: 1.20MM; Mfr_name: TEXAS INSTRUMENTS; Mfr_part_number: SN74AVC8T245RHLR; Mistral Part No: 143011040001-R; Package: QFN24; Part_type: ICS\TELECOM\TRANSCEIVER; Project: OMAPL1_PEC20; RoHS: RoHS; Temperature: -40°C+85°C; Tolerance: NA; Voltage: NA; Wattage: NA; Weight: NA; Datasheet: Y:\MIS_DATABASE\DATASHEETS\ICS\DIGITAL\BUSTRANSCEIVER\SN74AVC8T245.PDF
C343 C344 = CAP: CAP CERAMIC 47uF 16V 20% X5R 1206; Chkd/date: JAGADEESWARAN.S/250414; Crtd /date: BAVISH/010611; Custom_Duty: 15%; Customs_HS_Code: 85322990; Distributor_name: DIGIKEY; Distributor_part_number: 445-6003-1-ND; Height: 1.80MM; Mfr_name: TDK CORPORATION; Mfr_part_number: C3216X5R1C476M; Mistral Part No: 120011060001-R; Package: 1206; Part_type: CAPACITORS\CERAMIC; Project: TE_MODULE; RoHS: RoHS; Temperature: -55°C+85°C; Tolerance: 20%; Voltage: 16V; Wattage: NA; Weight: NA; Datasheet: Y:\MIS_DATABASE\DATASHEETS\CAPACITORS\TDK-C3216.PDF
J32 J33 = CON_AUDIOJACK4_SJ-2504N: CON AUDIO JACK 4POS FEMALE RT SMD; Chkd/date: VASANTHA/210714; Crtd /date: SARANYA/080514; Custom_Duty: 24%; Customs_HS_Code: 85369090; Distributor_name: NA; Distributor_part_number: NA; Height: 5.17MM; Mfr_name: CUI INC; Mfr_part_number: SJ-3524-SMT-1; Mistral Part No: 150014050028-R; Package: SMD; Part_type: CONNECTOR\JACK; Project: AEGIS GP BETA2; RoHS: RoHS; Temperature: -25°C+85°C; Tolerance: NA; Voltage: NA; Wattage: NA; Weight: NA; Datasheet: Y:\MIS_DATABASE\DATASHEETS\CONNECTORS\SJ-3524-SMT-1.PDF
R536 = RESISTOR: RES 0E 1/10W 5% 0402; Chkd/date: NAVEED/241114; Crtd /date: NAVEED/201014; Custom_Duty: 15%; Customs_HS_Code: 85332119; Distributor_name: DIGIKEY; Distributor_part_number: P0.0JCT-ND; Height: 0.40MM; Loading: DNI; Mfr_name: PANASONIC-ECG; Mfr_part_number: ERJ-2GE0R00X; Mistral Part No: 110014100008-R; Package: 0402; Part_type: RESISTORS\FIXED; Project: AEGIS POM; RoHS: RoHS; Tolerance: 5%; Wattage: 1/10W; Datasheet: Y:\MIS_DATABASE\DATASHEETS\RESISTORS\ERJ12.PDF
U75 = OSC_CB3LV_SMD4: OSC 12.288MHz SMD; Chkd/date: NAVEED/241114; Crtd /date: VASANTHA/111114; Custom_Duty: 24%; Customs_HS_Code: 85437099; Distributor_name: DIGIKEY; Distributor_part_number: CTX266LVCT-ND; Height: 1.80MM; Mfr_name: CTS; Mfr_part_number: CB3LV-3C-12M2880; Mistral Part No: 130014110012-R; Package: SMD; Part_type: OSCILLATORS; Project: GALILEO_EVM; RoHS: RoHS; Temperature: -20°C+70°C; Tolerance: NA; Voltage: NA; Wattage: NA; Weight: NA; Datasheet: Y:\MIS_DATABASE\DATASHEETS\MISC\CRY_OSC\CB3.PDF
U96 = TLV320AIC3106IRGZT_VQFN48: IC LOW-POWER STEREO AUDIO CODEC VQFN48; Chkd/date: SUHAS/261010; Crtd /date: MUDDU/150610; Custom_Duty: 15%; Customs_HS_Code: 85423100; Distributor_name: DIGIKEY; Distributor_part_number: TLV320AIC3106IRGZT-ND; Height: 1.00MM; Mfr_name: TEXAS INSTRUMENTS; Mistral Part No: 143010060003-R; Package: VQFN48; Part_type: ICS\TELECOM\CODEC; Project: CENTAURUS; RoHS: Sb/ Br FREE; Temperature: -40°C+85°C; Weight: NA; Datasheet: Y:\MIS_DATABASE\DATASHEETS\ICS\TELECOM\TLV320AIC3106IRGZT.PDF
R748 R787 = RESISTOR: RES 100E 1/16W 5% 0402; Chkd/date: VASANTHA/200614; Crtd /date: NAVEED/170614; Custom_Duty: 15%; Customs_HS_Code: 85332119; Distributor_name: DIGIKEY; Distributor_part_number: RMCF0402JT100RCT-ND; Height: 0.40MM; Mfr_name: STACKPOLE ELECTRONICS; Mfr_part_number: RMCF0402JT100R; Mistral Part No: 110014060039-R; Package: 0402; Part_type: RESISTORS\FIXED; Project: AEGIS_POM; RoHS: RoHS; Temperature: -55°C+155°C; Tolerance: 5%; Voltage: NA; Wattage: 1/16W; Weight: NA; Datasheet: Y:\MIS_DATABASE\DATASHEETS\RESISTORS\RMCF-SERIES1.PDF
SW11 SW15 = SW2: SWITCH DIP SPST LOW PROFILE SMD; Chkd/date: SARANYA/110314; Crtd /date: JAGADISH/280214; Custom_Duty: 24%; Customs_HS_Code: 85369090; Distributor_name: DIGIKEY; Distributor_part_number: CKN10358-ND; Height: 4.45MM; Mfr_name: C&K COMPONENTS; Mistral Part No: 130014030014-R; Package: SMD; Part_type: ELECTRO-MECHANICAL\SWITCH; Project: DMP; RoHS: RoHS; Temperature: -40°C+85°C; Tolerance: NA; Voltage: NA; Wattage: NA; Weight: NA; Datasheet: Y:\MIS_DATABASE\DATASHEETS\MISC\SWITCHES\SDAXXX_SERIES.PDF
U135 U137 = SN74AVC1T45DBVR_SOT23-6: IC SINGLE-BIT DUAL-SUPPLY BUS TRANSCEIVER SOT23-6; Chkd/date: MAZHAR/050208; Crtd /date: USMAN/050208; Custom_Duty: 15%; Customs_HS_Code: 85423100; Distributor_name: DIGIKEY; Distributor_part_number: 296-19094-1-ND; Height: 1.45MM; Mfr_name: TEXAS INSTRUMENTS; Mistral Part No: 141009030019-R; Part_type: ICS\DIGITAL\BUSTRANSCEIVER; Project: HS100RD; RoHS: RoHS; Datasheet: Y:\MIS_DATABASE\DATASHEETS\ICS\DIGITAL\BUSTRANSCEIVER\SN74AVC1T45.PDF
U142 = TXS0108EPW_TSSOP20: IC TRANSLATOR BIDIRECTIONAL VOLTAGE-LEVEL 8BIT TSSOP20; Chkd/date: BAVISH/111011; Crtd /date: CHAITHANYA/111011; Custom_Duty: 15%; Customs_HS_Code: 85423100; Distributor_name: DIGIKEY; Distributor_part_number: 296-23011-1-ND; Height: 1.20MM; Mfr_name: TEXAS INSTRUMENTS; Mistral Part No: 141011100005-R; Package: TSSOP20; Part_type: ICS\INTERFACE; Project: CENTAURUS_CATALOG; RoHS: RoHS; Temperature: -40°C+85°C; Tolerance: NA; Voltage: NA; Wattage: NA; Weight: NA; Datasheet: Y:\MIS_DATABASE\DATASHEETS\ICS\INTERFACE\TXS0108E.PDF

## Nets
DGND: C294.1 C307.2 C315.2 C316.2 C319.2 C324.2 C325.2 C326.2 C645.1 C651.2 C652.2 C674.2 C676.1 C679.2 C683.2 C684.2 C689.2 C692.1 C693.2 C694.2 C697.2 C698.2 C699.2 C700.2 C701.2 C704.1 C706.1 C707.2 C733.1 C735.2 C785.1 C786.2 C789.1 C790.1 C791.2 C812.1 C813.2 C815.2 FB41.2 FB42.1 J36.2 J36.5 J36.8 J36.11 J36.17 R490.1 R502.1 R535.1 R748.1 R756.1 R758.2 R764.2 R765.2 R771.1 R787.1 R812.2 R827.2 R873.2 R902.2 R903.2 R911.1 R913.1 U64.8(GND1) U64.9(GND2) U69.8(GND1) U69.9(GND2) U75.2(GND) U84.3(GND) U91.3(GND) U96.42(DVSS) U96.43(SELECT) U97.3(GND) U102.43(CGND) U102.55(RSVDL) U102.57(IOGND) U102.63(AGND) U102.70(VDDQ) U102.73(PAD) U103.2(GND) U108.6(GND1) U108.14(GND2) U108.19(GND3) U115.11(GND1) U115.12(GND2) U115.13(GND3) U115.25(EP) U135.2(GND) U136.8(GND1) U136.9(GND2) U137.2(GND) U142.11(GND) U144.3(GND) ; also on sheet 1 11 12 13 14 15 16 17 18 19 20 21 25 26 27 28 29 30 31 32 33 34 35 36 37 38 39 40 41 42 43 44 45 46 47 48 49 50
GND_HDMI: FB42.2 J36.20 J36.21 J36.22 J36.23
V5_0HDMICONN: C707.1 J36.18 U108.13(5V_OUT)
VCC1V2: C315.1 C699.1 C735.1 FB35.2 FB39.2 U103.5(OUT)
VCC1V8_AUD: C326.1 C679.1 R536.2 R543.2 U96.36(DVDD.1)
VCC3V3_AUD: C294.2 C316.1 C339.1 C674.1 C692.2 C695.1 C696.1 C702.1 R503.1 R534.1 R755.1 R894.2 U75.4(VCC) U96.16(DRVDD.1) U96.17(DRVDD.2) U96.24(DRVDD.3) U96.25(AVDD_DAC) U96.44(IOVDD) U97.5(VCC)
VCC3V3_DCIN: C645.2 C785.2 C786.1 C789.2 C790.2 C791.1 R491.1 R492.1 R555.1 R750.1 R796.1 R870.1 R874.1 R894.1 R910.1 R912.1 U64.1(VCCA) U64.16(VCCB) U135.1(VCCA) U135.6(VCCB) U136.1(VCCA) U136.16(VCCB) U137.1(VCCA) U137.6(VCCB) ; also on sheet 11 17 18 19 20 21 25 26 27 28 29 30 31 32 33 34 35 36 37 38 43 44 45 46 47 48 50
VCC3V3_HDMI: C307.1 C324.1 C651.1 C652.1 C676.2 C706.2 C733.2 FB38.2 R555.2 R561.1 R742.1 R772.1 R813.1 U69.1(VCCA) U69.16(VCCB) U84.5(VCC) U91.5(VCC) U108.24(VCCA) U115.1(VCCA) U115.23(VCCB1) U115.24(VCCB2)
VCC3V3_WLAN: C815.1 U144.5(VCC) ; also on sheet 30
VCC5V0_DCDC: R568.1 ; also on sheet 21 27 30 44 46 48 49 50
VCC5V0_HDMI: C697.1 C704.2 R568.2 U103.1(IN) U108.11(VCC5V)
AUD_AGND: C339.2 C687.1 C691.1 C695.2 C696.2 C702.2 FB41.1 J32.1(S) J33.1(S) U96.15(AVSS_ADC) U96.20(DRVSS.1) U96.21(DRVSS.2) U96.26(AVSS_DAC) U96.49(TPAD)
AUD_BUFF_CLK_DIR: R492.2 R502.2 U136.2(1DIR)
AUD_BUFF_DAT_DIR: R910.2 R911.2 U136.3(2DIR)
AUD_BUFF_EN: R796.2 SW15.2 U136.14(~{2OE}) U136.15(~{1OE})
AUD_MCLK_R: R537.2 U96.37(MCLK)
AUDIO_RSTn: U97.1(A) ; also on sheet 47
AUDIO_RSTn_AND: U96.33(~{RESET}) U97.4(Y)
BUF_MCASP0AHCLKX: R876.1 ; also on sheet 33
BUF_McASP2ACLKX: TP193.1(TP) U69.5(1A2) U96.38(BCLK) U136.13(1B1)
BUF_MCASP2AXR2: TP206.1(TP) U69.7(2A2) U96.40(DIN) U136.11(2B1)
BUF_MCASP2AXR3: R762.2 TP207.1(TP) U137.3(A)
BUF_McASP2FSX: TP205.1(TP) U69.6(2A1) U96.39(WCLK) U136.12(1B2)
BUF_MMC1_CLK: U142.20(B1) ; also on sheet 18
BUF_MMC1_CMD: U142.18(B2) ; also on sheet 18
BUF_MMC1_DAT0: U142.17(B3) ; also on sheet 18
BUF_MMC1_DAT1: U142.16(B4) ; also on sheet 18
BUF_MMC1_DAT2: U142.15(B5) ; also on sheet 18
BUF_MMC1_DAT3: U142.14(B6) ; also on sheet 18
COM8_AUD_CLK: U64.4(1A1) ; also on sheet 30
COM8_AUD_FSYNC: U64.5(1A2) ; also on sheet 30
COM8_BUFF_CLK_DIR: R490.2 R491.2 U64.2(1DIR)
COM8_BUFF_DAT_DIR: R912.2 R913.2 U64.3(2DIR)
COM8_BUFF_EN: R750.2 SW11.2 U64.14(~{2OE}) U64.15(~{1OE})
COM8_MCASP2AXR1: U135.4(B) ; also on sheet 30
COM8_MCASP2AXR4: U64.6(2A1) ; also on sheet 30
COM8_MMC1_CLK: U142.1(A1) ; also on sheet 30
COM8_MMC1_CMD: U142.3(A2) ; also on sheet 30
COM8_MMC1_DAT0: U142.4(A3) ; also on sheet 30
COM8_MMC1_DAT1: U142.5(A4) ; also on sheet 30
COM8_MMC1_DAT2: U142.6(A5) ; also on sheet 30
COM8_MMC1_DAT3: U142.7(A6) ; also on sheet 30
DC_BRD_DET: R806.2 U69.14(~{2OE}) U69.15(~{1OE}) ; also on sheet 12 33 45
DC_BRD_DET_INV: U84.4(Y) U115.22(~{OE})
HDMI_AC_BIAS_EN: U102.33(DE) ; also on sheet 20
HDMI_AUDBCLK: TP213.1(TP) U69.12(1B2) U102.45(SCK) U115.20(B2)
HDMI_AUDD0: TP208.1(TP) U69.10(2B2) U102.41(SD0) U115.18(B4)
HDMI_AUDD1: TP209.1(TP) U102.40(SD1) U115.16(B6)
HDMI_AUDD2: TP210.1(TP) U102.39(SD2) U115.15(B7)
HDMI_AUDD3: TP211.1(TP) U102.37(SD3) U115.14(B8)
HDMI_AUDFSX: TP214.1(TP) U69.11(2B1) U102.44(WS) U115.19(B3)
HDMI_AUDIO_MSTRCLK: R500.2 R537.1 U75.3(OUTPUT)
HDMI_AUDMCLK: TP212.1(TP) U69.13(1B1) U102.38(MCLK) U115.21(B1)
HDMI_CEC: U102.71(CEC_A) U108.1(CEC_A)
HDMI_CEC_D: TP166.1(TP) U102.50(CEC_D)
HDMI_CLK+: J36.10 U102.59(TXC+) U108.16(CLK+)
HDMI_CLK-: J36.12 U102.58(TXC-) U108.15(CLK-)
HDMI_DATA0: U102.32(D0) ; also on sheet 20
HDMI_DATA1: U102.31(D1) ; also on sheet 20
HDMI_DATA2: U102.30(D2) ; also on sheet 20
HDMI_DATA3: U102.29(D3) ; also on sheet 20
HDMI_DATA4: U102.28(D4) ; also on sheet 20
HDMI_DATA5: U102.27(D5) ; also on sheet 20
HDMI_DATA6: U102.25(D6) ; also on sheet 20
HDMI_DATA7: U102.24(D7) ; also on sheet 20
HDMI_DATA8: U102.23(D8) ; also on sheet 20
HDMI_DATA9: U102.20(D9) ; also on sheet 20
HDMI_DATA10: U102.19(D10) ; also on sheet 20
HDMI_DATA11: U102.18(D11) ; also on sheet 20
HDMI_DATA12: U102.17(D12) ; also on sheet 20
HDMI_DATA13: U102.16(D13) ; also on sheet 20
HDMI_DATA14: U102.15(D14) ; also on sheet 20
HDMI_DATA15: U102.14(D15) ; also on sheet 20
HDMI_DATA16: U102.13(D16) ; also on sheet 20
HDMI_DATA17: U102.11(D17) ; also on sheet 20
HDMI_DATA18: U102.10(D18) ; also on sheet 20
HDMI_DATA19: U102.9(D19) ; also on sheet 20
HDMI_DATA20: U102.8(D20) ; also on sheet 20
HDMI_DATA21: U102.7(D21) ; also on sheet 20
HDMI_DATA22: U102.6(D22) ; also on sheet 20
HDMI_DATA23: U102.4(D23) ; also on sheet 20
HDMI_EXTSWING: R765.1 U102.56(EXT_SWING)
HDMI_HPLG: R764.1 U102.54(HPD) U108.4(HPD_A)
HDMI_HSYNC: U102.34(HSYNC) ; also on sheet 20
HDMI_I2CSCL: R562.2 U102.49(DSCL) U108.2(SCL_A)
HDMI_I2CSDA: R769.2 U102.48(DSDA) U108.3(SDA_A)
HDMI_INTn: R556.2 U102.52(INT) ; also on sheet 12
HDMI_PCLK: U102.22(IDCK) ; also on sheet 20
HDMI_RSTn: U91.1(A) ; also on sheet 47
HDMI_RSTn_AND: U91.4(Y) U102.51(RESET#)
HDMI_TX0+: J36.7 U102.62(TX0+) U108.18(D0+)
HDMI_TX0-: J36.9 U102.61(TX0-) U108.17(D0-)
HDMI_TX1+: J36.4 U102.65(TX1+) U108.21(D1+)
HDMI_TX1-: J36.6 U102.64(TX1-) U108.20(D1-)
HDMI_TX2+: J36.1 U102.68(TX2+) U108.23(D2+)
HDMI_TX2-: J36.3 U102.67(TX2-) U108.22(D2-)
HDMI_VSYNC: U102.35(VSYNC) ; also on sheet 20
HDMICONN_CEC: J36.13 U108.7(CEC_B)
HDMICONN_HPLG: J36.19 U108.10(HPD_B)
HDMICONN_I2CSCL: J36.15 U108.8(SCL_B)
HDMICONN_I2CSDA: J36.16 U108.9(SDA_B)
LDO1_1V8: C813.1 R536.1 U142.19(VCCB) ; also on sheet 13 18 30 36 48
LDO2_1V8: C812.2 R543.1 U142.2(VCCA) ; also on sheet 30 48
MFP0: R535.2 R755.2 U96.45(MFP0)
MFP1: R534.2 R756.2 U96.46(MFP1)
MFP2: TP164.1(TP) U96.47(MFP2)
MFP3: TP165.1(TP) U96.48(MFP3)
SOC_I2C1_SCL: U96.1(SCL) U102.1(CSCL) ; also on sheet 21 33 35 37
SOC_I2C1_SDA: U96.2(SDA) U102.2(CSDA) ; also on sheet 21 33 35 37
SOC_MCASP0ACLKX: U115.4(A2) ; also on sheet 33
SOC_MCASP0AXR0: U115.6(A4) ; also on sheet 33
SOC_MCASP0AXR1: U115.8(A6) ; also on sheet 33
SOC_MCASP0AXR2: U115.9(A7) ; also on sheet 33
SOC_MCASP0AXR3: U115.10(A8) ; also on sheet 33
SOC_MCASP0FSX: U115.5(A3) ; also on sheet 33
SOC_McASP2ACLKX: U64.13(1B1) U136.4(1A1) ; also on sheet 33
SOC_MCASP2AXR1: U135.3(A) ; also on sheet 33
SOC_MCASP2AXR2: U136.6(2A1) ; also on sheet 33
SOC_MCASP2AXR3: U137.4(B) ; also on sheet 33
SOC_MCASP2AXR4: U64.11(2B1) ; also on sheet 33
SOC_McASP2FSX: U64.12(1B2) U136.5(1A2) ; also on sheet 33
SOC_RESETSTATz: U91.2(B) U97.2(B) ; also on sheet 11 17 18 21 25 26 31 33 45 46
VHDMI_AVCC12: C319.1 C683.1 C684.1 FB35.1 U102.60(AVCC12_1) U102.66(AVCC12_2)
VHDMI_CVCC12: C689.1 C694.1 C698.1 C700.1 FB39.1 U102.5(CVCC12_1) U102.12(CVCC12_2) U102.26(CVCC12_3) U102.42(CVCC12_4) U102.47(CVCC12_5) U102.53(CVCC12_6)
VHDMI_IOVCC: C325.1 C693.1 C701.1 FB38.1 R556.1 R562.1 R766.1 R769.1 U102.3(IOVCC1) U102.21(IOVCC2) U102.46(IOVCC3)
WLAN_TRANS_EN: U144.2(A) ; also on sheet 30 33
WLAN_TRANS_EN_INV: U142.10(OE) U144.4(Y)
N14056347: R771.2 U102.36(SPDIF)
N14056377: R772.2 U108.5(LS_OE) U108.12(CT_HPD)
N14056401: R766.2 U102.72(CI2CA)
N14057055: R561.2 U103.3(EN)
N14058041: R758.1 U102.69(IO_SEL)
N14060680: C344.2 U96.23(HPROUT)
N14060684: C344.1 J33.3(T)
N14060688: C343.2 U96.18(HPLOUT)
N14060756: C328.2 U96.3(LINE1L+)
N14060760: C332.2 U96.5(LINE1R+)
N14060764: C332.1 J32.3(T)
N14060776: C328.1 J32.2(TS)
N14060794: C343.1 J33.2(TS)
N14060830: C687.2 U96.4(LINE1L-)
N14060838: C691.2 U96.6(LINE1R-)
N14061510: R762.1 U96.41(DOUT)
N17484568: R813.2 U115.2(DIR)
N18055312: TP169.1(TP) U96.7(LINE2L+)
N18055326: TP170.1(TP) U96.8(LINE2L-)
N18055702: TP172.1(TP) U96.19(HPLCOM)
N18055705: TP173.1(TP) U96.22(HPRCOM)
N18068201: TP168.1(TP) U96.35(GPIO1)
N18068219: TP167.1(TP) U96.34(GPIO2)
N22515669: R503.2 U75.1(EOH)
N22519288: R742.2 U69.2(1DIR) U69.3(2DIR)
N22525689: R806.1 U84.2(A)
N22894279: R827.1 U115.7(A5)
N22896034: R876.2 U115.3(A1)
N22896196: R500.1 U69.4(1A1)
N23992168: R873.1 U136.7(2A2)
N23992275: R787.2 SW15.1
N23992339: R874.2 U137.5(DIR)
N23995153: R812.1 U64.7(2A2)
N23995260: R748.2 SW11.1
N23995326: R870.2 U135.5(DIR)
N26212205: R903.1 U142.8(A7) U142.9(A8)
N26212363: R902.1 U142.12(B8) U142.13(B7)

Not connected (* = marked no-connect by the designer): J32 4(R)*; J33 4(R)*; J36 14*; U64 10(2B2)*; U84 1(NC)*; U96 9(LINE2R+)* 10(LINE2R-)* 11(MIC3L)* 12(MICDET)* 13(MICBIAS)* 14(MIC3R)* 27(MONO_LO+)* 28(MONO_LO-)* 29(LEFT_LO+)* 30(LEFT_LO-)* 31(RIGHT_LO+)* 32(RIGHT_LO-)*; U103 4(NR/FB)*; U115 17(B5)*; U136 10(2B2)*; U144 1(NC)*

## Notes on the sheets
sheet 22
- HDMI TRANSMITTER
- HDMI Audio Line selection between McASP0
  & McASP2
- DC_BRD_DET
- AUDIO LINE
  SELECTED
- L
- McASP2
- H
- McASP0
- I2C ADDRESS: 0x3B, 0x3F, 0x62
- HDMI CONNECTOR
- HDMI 1.2V GENERATION
- HDMI ESD DEVICE
- NOTE:
  TPD12S016PWR has integrated pullup or pulldown resistors on the
  I2C and HPD lines  hence no external pullup or pulldown required.
sheet 23
- AUDIO CODEC
- AUDIO CODEC RESET
- CODEC I2C ADDRESS SELECTION
- MFP0
- MFP1
- ADDRESS
- L
- L
- 1A
- L
- H
- 1B
- H
- L
- 1C
- I2C ADDRESS: 0x1B
- H
- H
- 1D
sheet 24
- AUDIO BUFFER
- AUD BUFFER SELECTION
- SW15
- SELECTION
- ON
- AUDIO CODEC
- OFF
- COM8
- COM8 SDIO BUFFER
- COM8 BUFFER
- COM8 BUFFER SELECTION
- SW11
- SELECTION
- OFF
- AUDIO CODEC
- ON
- COM8
